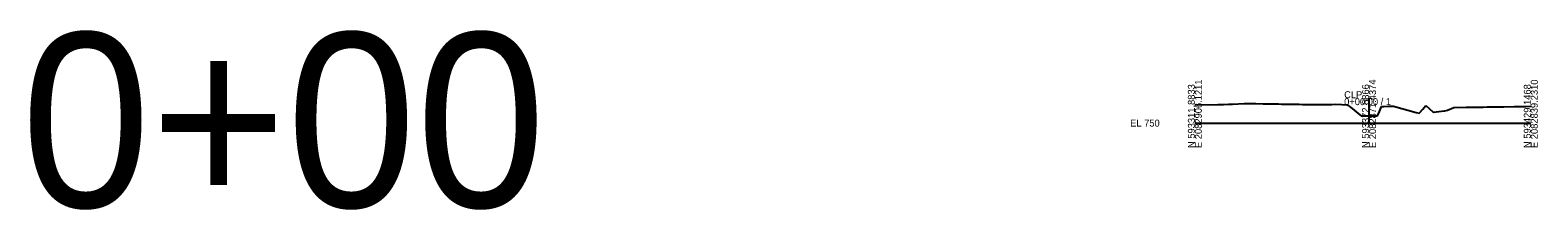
# Model space of a CAD drawing. Extents: x -577 to 1138, y -35 to 4556.
# Drawn here: x -468 to 138, y -35 to 37 of the extents above; entities that cross this region are included whole.
import ezdxf

# ---------------------------------------------------------------- set-up
doc = ezdxf.new("R2010")
doc.units = 0
for name, color, linetype in [('GK_Cells', 7, 'Continuous'), ('SC_Scratch1', 7, 'Continuous'), ('XS_X_Ground_Line', 7, 'Continuous')]:
    doc.layers.add(name, color=color, linetype=linetype)

msp = doc.modelspace()

# ---------------------------------------------------------------- linework, layer by layer
at = {"layer": 'GK_Cells'}
for p, q in [((70, 0), (70, 10)), ((0, 0), (70, 0)), ((70, 0), (135, 0))]:
    msp.add_line(p, q, dxfattribs=at)
at = {"layer": 'XS_X_Ground_Line'}
for p, q in [((0, 7.3), (9.17, 7.49)), ((9.17, 7.49), (11.49, 7.49)), ((11.49, 7.49), (13.5, 7.53)), ((13.5, 7.53), (15.12, 7.62)), ((15.12, 7.62), (19.85, 7.88)), ((19.85, 7.88), (23.54, 7.88)), ((23.54, 7.88), (24.49, 7.86)), ((24.49, 7.86), (27.4, 7.73)), ((27.4, 7.73), (27.55, 7.73)), ((27.55, 7.73), (27.99, 7.72)), ((27.99, 7.72), (28.37, 7.71)), ((28.37, 7.71), (33.62, 7.68)), ((33.62, 7.68), (34.86, 7.66)), ((34.86, 7.66), (37.22, 7.61)), ((37.22, 7.61), (38.72, 7.58)), ((38.72, 7.58), (41.98, 7.55)), ((41.98, 7.55), (43.29, 7.47)), ((43.29, 7.47), (49.8, 7.43)), ((49.8, 7.43), (53.16, 7.41)), ((53.16, 7.41), (53.54, 7.42)), ((53.54, 7.42), (55.08, 7.41)), ((55.08, 7.41), (56.4, 7.58)), ((56.4, 7.58), (59.13, 7.47)), ((59.13, 7.47), (61.26, 7.39)), ((61.26, 7.39), (61.5, 7.19)), ((61.5, 7.19), (62.13, 6.68)), ((62.13, 6.68), (62.49, 6.39)), ((62.49, 6.39), (66.24, 3.33)), ((74.16, 4.65), (75, 6.71)), ((75, 6.71), (75.81, 6.67)), ((75.81, 6.67), (75.96, 6.67)), ((75.96, 6.67), (77.87, 6.76)), ((77.87, 6.76), (79.8, 6.84)), ((79.8, 6.84), (88.94, 4.28)), ((91.58, 5.65), (92.64, 6.88)), ((92.64, 6.88), (92.77, 7.02)), ((92.77, 7.02), (95.68, 4.56)), ((101.56, 5.25), (104.04, 6.27)), ((104.04, 6.27), (108.99, 6.34)), ((108.99, 6.34), (110.15, 6.36)), ((110.15, 6.36), (112.98, 6.4)), ((112.98, 6.4), (115.83, 6.44)), ((115.83, 6.44), (117.43, 6.48)), ((117.43, 6.48), (117.71, 6.48)), ((117.71, 6.48), (122.83, 6.55)), ((122.83, 6.55), (124.15, 6.57)), ((124.15, 6.57), (128.26, 6.62)), ((128.26, 6.62), (129.99, 6.64)), ((129.99, 6.64), (130.68, 6.65)), ((130.68, 6.65), (131.54, 6.66)), ((131.54, 6.66), (132.96, 6.68)), ((132.96, 6.68), (135, 6.74)), ((66.24, 3.33), (66.86, 2.98)), ((66.86, 2.98), (67.63, 2.97)), ((67.63, 2.97), (72.98, 2.91)), ((72.98, 2.91), (73.45, 2.88)), ((73.45, 2.88), (73.54, 3.12)), ((73.54, 3.12), (74.16, 4.65)), ((88.94, 4.28), (90.08, 3.96)), ((90.08, 3.96), (90.11, 3.95)), ((90.11, 3.95), (90.27, 4.14)), ((90.27, 4.14), (91.58, 5.65)), ((95.68, 4.56), (95.74, 4.51)), ((95.74, 4.51), (95.82, 4.45)), ((95.82, 4.45), (95.89, 4.38)), ((95.89, 4.38), (95.92, 4.36)), ((95.92, 4.36), (100.25, 4.91)), ((100.25, 4.91), (100.37, 4.94)), ((100.37, 4.94), (100.5, 4.97)), ((100.5, 4.97), (100.95, 5.09)), ((100.95, 5.09), (101.56, 5.25))]:
    msp.add_line(p, q, dxfattribs=at)

# ---------------------------------------------------------------- texts
at = {"layer": 'GK_Cells'}
for s, p in [('N 593311.8833', (0, -10)), ('E 2082906.1211', (2.8, -10)), ('N 593372.6866', (70, -10)), ('E 2082871.4374', (72.8, -10)), ('N 593429.1468', (135, -10)), ('E 2082839.2310', (137.8, -10))]:
    msp.add_text(s, height=2.8, rotation=90, dxfattribs=at).set_placement(p)
for s, p in [('CLP_', (60, 10)), ('0+00.00 / 1', (60, 7.2)), ('EL 750', (-26, -1.4))]:
    msp.add_text(s, height=2.8, dxfattribs=at).set_placement(p)
at = {"layer": 'SC_Scratch1'}
msp.add_text('0+00', height=70, dxfattribs=at).set_placement((-471.72, -33.78))

doc.saveas('drawing.dxf')
